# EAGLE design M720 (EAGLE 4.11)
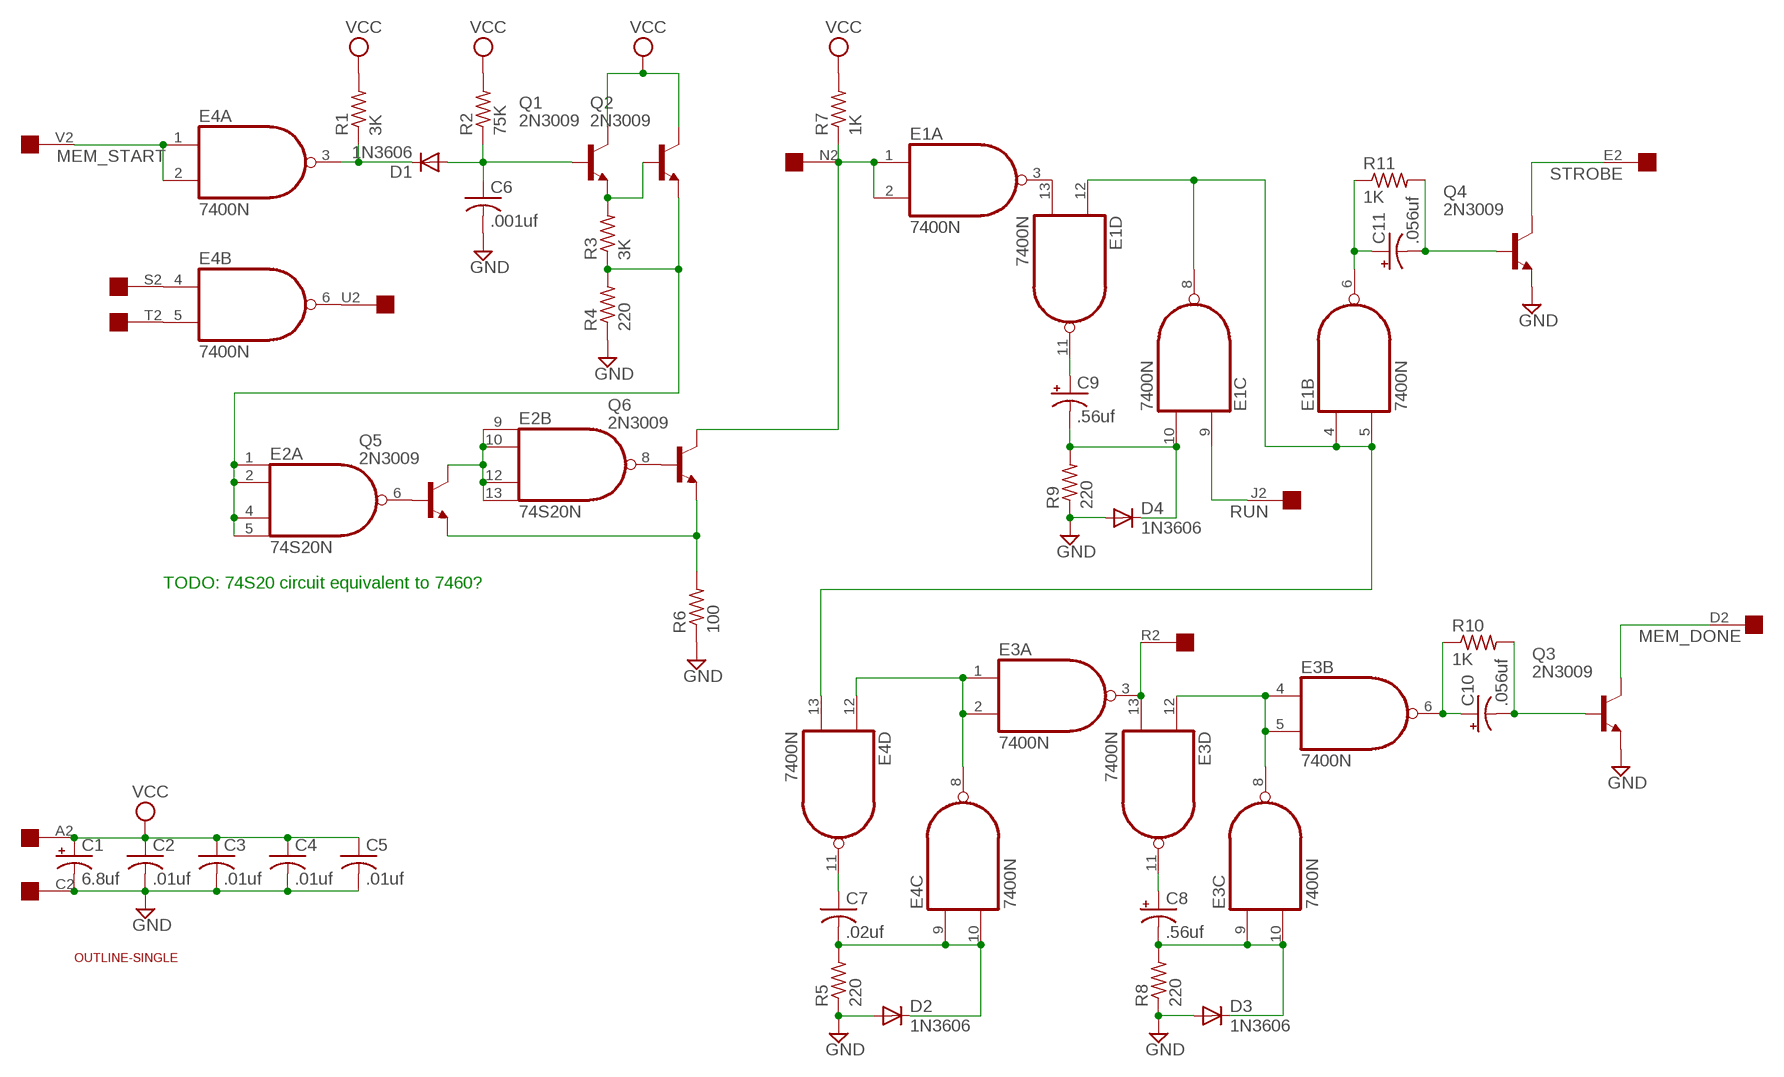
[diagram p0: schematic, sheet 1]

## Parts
C1  6.8uf  CPOL-USE15-5AXIAL  [E15-5]
C2  .01uf  C-US050-025X075  [C050-025X075]
C3  .01uf  C-US050-025X075  [C050-025X075]
C4  .01uf  C-US050-025X075  [C050-025X075]
C5  .01uf  C-US050-025X075  [C050-025X075]
C6  .001uf  C-US050-025X075  [C050-025X075]
C7  .02uf  C-US050-025X075  [C050-025X075]
C8  .56uf  CPOL-USB45181C  [B45181C]
C9  .56uf  CPOL-USB45181C  [B45181C]
C10  .056uf  CPOL-USB45181C  [B45181C]
C11  .056uf  CPOL-USB45181C  [B45181C]
D1  1N3606  1N4148  [DO35-10]
D2  1N3606  1N4148  [DO35-10]
D3  1N3606  1N4148  [DO35-10]
D4  1N3606  1N4148  [DO35-10]
E1  7400N  [DIL14]
E2  74S20N  [DIL14]
E3  7400N  [DIL14]
E4  7400N  [DIL14]
Q1  2N3009  2N2405  [TO5]
Q2  2N3009  2N2405  [TO5]
Q3  2N3009  2N2405  [TO5]
Q4  2N3009  2N2405  [TO5]
Q5  2N3009  2N2405  [TO5]
Q6  2N3009  2N2405  [TO5]
R1  3K  R-US_0207/10  [0207/10]
R2  75K  R-US_0207/10  [0207/10]
R3  3K  R-US_0207/10  [0207/10]
R4  220  R-US_0207/10  [0207/10]
R5  220  R-US_0207/10  [0207/10]
R6  100  R-US_0207/10  [0207/10]
R7  1K  R-US_0207/10  [0207/10]
R8  220  R-US_0207/10  [0207/10]
R9  220  R-US_0207/10  [0207/10]
R10  1K  R-US_0207/10  [0207/10]
R11  1K  R-US_0207/10  [0207/10]
U$1  OUTLINE-SINGLE  [SINGLE]
U$3  EDGE-1  [EDGE-CON1]

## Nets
GND [supply]: C1.- C2.2 C3.2 C4.2 C5.2 C6.2 D2.A D3.A D4.A Q3.1(E) Q4.1(E) R4.1 R5.1 R6.1 R8.1 R9.1 U$3.C2
MEM_DONE: Q3.3(C) U$3.D2
MEM_START: E4.1(A:I0) E4.2(A:I1) U$3.V2
N$1: E2.1(A:I0) E2.2(A:I1) E2.4(A:I2) E2.5(A:I3) Q2.1(E) R3.1 R4.2
N$2: D1.C E4.3(A:O) R1.1
N$3: C6.1 D1.A Q1.2(B) R2.1
N$4: Q1.1(E) Q2.2(B) R3.2
N$5: E4.4(B:I0) U$3.S2
N$6: E4.5(B:I1) U$3.T2
N$7: E4.6(B:O) U$3.U2
N$8: E1.1(A:I0) E1.2(A:I1) Q6.3(C) R7.1 U$3.N2
N$9: E1.3(A:O) E1.13(D:I1)
N$10: E1.4(B:I0) E1.5(B:I1) E1.8(C:O) E1.12(D:I0) E4.13(D:I1)
N$11: C7.2 D2.C E4.9(C:I0) E4.10(C:I1) R5.2
N$12: C9.+ E1.11(D:O)
N$13: C9.- D4.C E1.10(C:I1) R9.2
N$14: C11.+ E1.6(B:O) R11.1
N$15: C11.- Q4.2(B) R11.2
N$16: E3.1(A:I0) E3.2(A:I1) E4.8(C:O) E4.12(D:I0)
N$17: C7.1 E4.11(D:O)
N$18: E3.3(A:O) E3.13(D:I1) U$3.R2
N$19: E3.4(B:I0) E3.5(B:I1) E3.8(C:O) E3.12(D:I0)
N$20: E2.8(B:O) Q6.2(B)
N$21: C8.- D3.C E3.9(C:I0) E3.10(C:I1) R8.2
N$22: C8.+ E3.11(D:O)
N$23: C10.+ E3.6(B:O) R10.1
N$24: C10.- Q3.2(B) R10.2
N$25: E2.6(A:O) Q5.2(B)
N$26: E2.9(B:I0) E2.10(B:I1) E2.12(B:I2) E2.13(B:I3) Q5.3(C)
N$28: Q5.1(E) Q6.1(E) R6.2
RUN: E1.9(C:I0) U$3.J2
STROBE: Q4.3(C) U$3.E2
VCC [supply]: C1.+ C2.1 C3.1 C4.1 C5.1 Q1.3(C) Q2.3(C) R1.2 R2.2 R7.2 U$3.A2
Unconnected: U$3.B2 U$3.F2 U$3.H2 U$3.K2 U$3.L2 U$3.M2 U$3.P2

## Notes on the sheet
- TODO: 74S20 circuit equivalent to 7460?

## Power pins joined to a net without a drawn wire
GND: E1.7(P:GND) E2.7(P:GND) E3.7(P:GND) E4.7(P:GND)
VCC: E1.14(P:VCC) E2.14(P:VCC) E3.14(P:VCC) E4.14(P:VCC)

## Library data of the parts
C1 C8-C11 = rcl:CPOL-US: POLARIZED CAPACITOR, American symbol
C2-C7 = rcl:C-US: CAPACITOR, American symbol
D1-D4 = diode:1N4148: DIODE
E1 E3 E4 = 74xx-us:74*00: Quad 2-input NAND gate
E2 = 74xx-us:74*20: Dual 4-input NAND gate
Q1-Q6 = transistor:2N2405: NPN TRANSISTOR
R1-R11 = rcl:R-US_: RESISTOR, American symbol
U$1 = dec-con:OUTLINE-*: Board outlines for DEC boards.
U$3 = dec-con:EDGE-1: Single-Sided DEC Edge Connector -- (side 2)

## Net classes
1 supply: width 0.762 mm, drill 0.508 mm

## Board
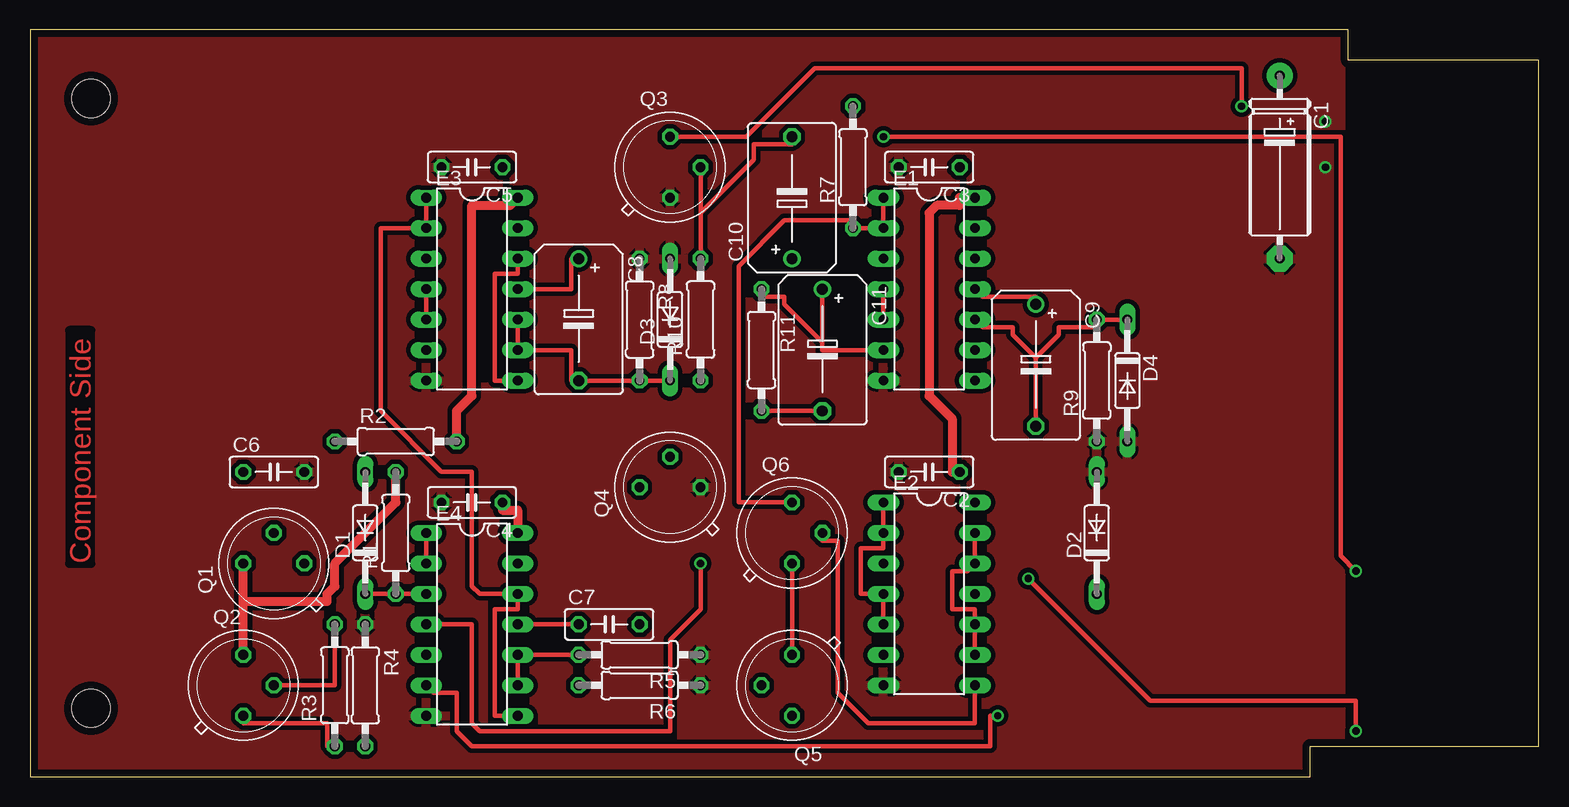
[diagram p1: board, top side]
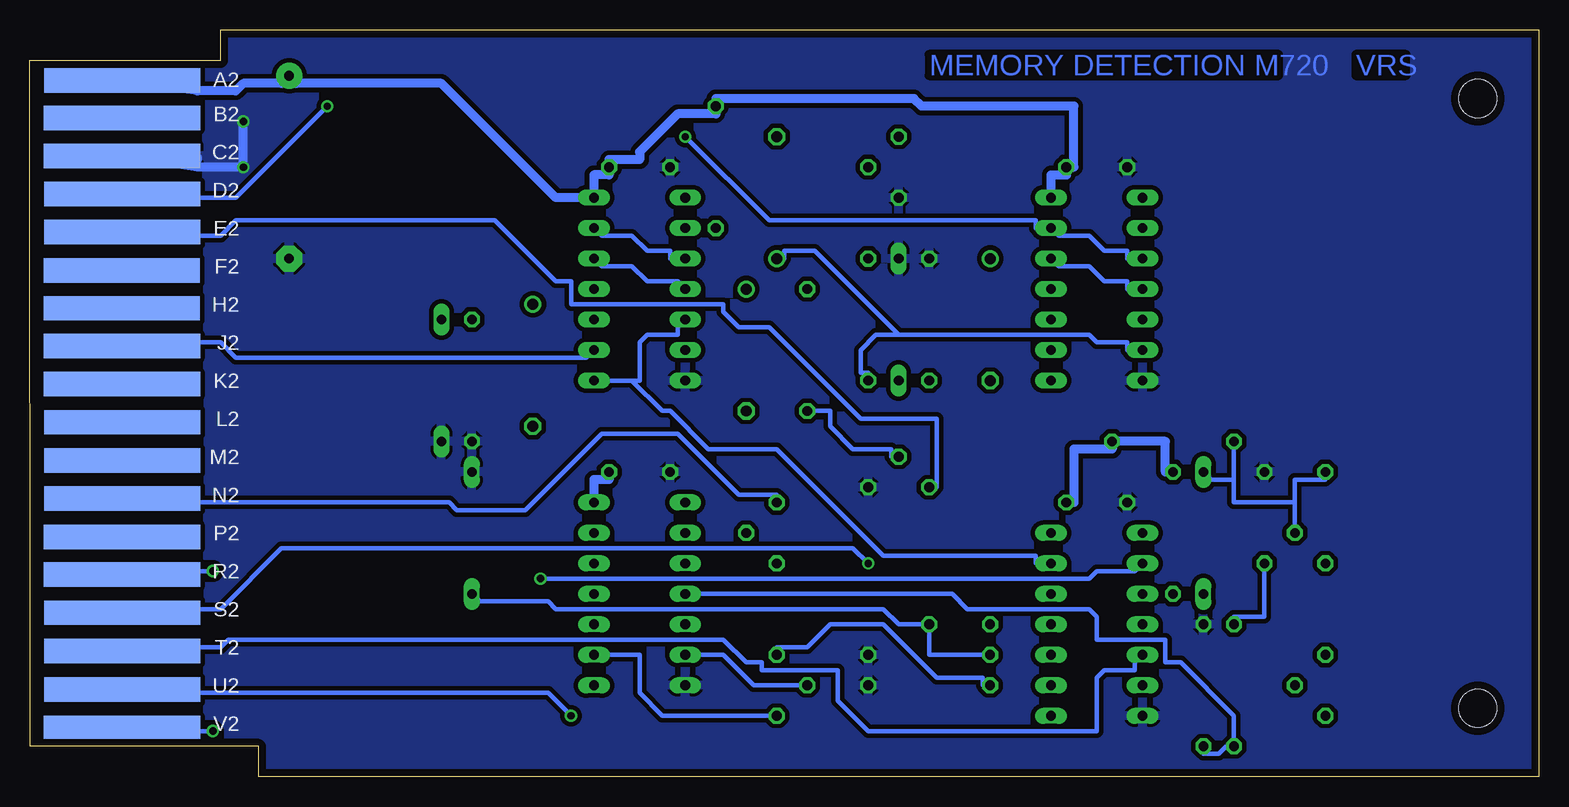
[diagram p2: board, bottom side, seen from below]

Size 125.73 x 62.23 mm. Coordinates in mm from the lower left corner, seen from the top.
Copper layers (1*16): Top 0.035mm / dielectric 1.5mm / Bottom 0.035mm
Design rules "15mils": minimum track width 15mil, minimum drill 24mil, track to track 15mil, track to pad 10mil, pad to pad 10mil, via to via 10mil, smd to smd 10mil, copper to edge 25mil, drill to drill 10mil, minimum pad ring 10mil, minimum via ring 8mil, stop-mask expansion 0mil, vias tented up to drill 0mil, thermal gap 10mil

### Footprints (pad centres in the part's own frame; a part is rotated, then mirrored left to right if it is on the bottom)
E15-5 = drill 0.813 pad 2.159 round: + -7.62,0 | drill 0.813 pad 2.159 octagon: - 7.62,0
C050-025X075 = drill 0.813 octagon: 1 -2.54,0; 2 2.54,0
B45181C = drill 0.914 round: + -5.08,0 | drill 0.914 octagon: - 5.08,0
DO35-10 = drill 0.813 long: A 5.08,0; C -5.08,0
DIL14 = drill 0.813 long: 1 -7.62,-3.81; 2 -5.08,-3.81; 3 -2.54,-3.81; 4 0,-3.81; 5 2.54,-3.81; 6 5.08,-3.81; 7 7.62,-3.81; 8 7.62,3.81; 9 5.08,3.81; 10 2.54,3.81; 11 0,3.81; 12 -2.54,3.81; 13 -5.08,3.81; 14 -7.62,3.81
TO5 = drill 0.813 octagon: 1 0,-2.54; 2 2.54,0; 3 0,2.54
0207/10 = drill 0.813 octagon: 1 -5.08,0; 2 5.08,0
SINGLE = hole 3.175: 120.65,56.515; 120.65,5.715
EDGE-CON1 = smd 13.017 x 2.032 bottom: A2 7.69,4.194; B2 7.668,7.328; C2 7.668,10.49; D2 7.693,13.665; E2 7.693,16.84; F2 7.642,20.041; H2 7.642,23.19; J2 7.668,26.34; K2 7.668,29.515; L2 7.693,32.69; M2 7.693,35.89; N2 7.693,39.04; P2 7.668,42.24; R2 7.668,45.39; S2 7.693,48.565; T2 7.693,51.74; U2 7.693,54.966 | smd 13.017 x 1.905 bottom: V2 7.668,58.102

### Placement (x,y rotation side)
C1  104.14,50.8 270 top
C2  74.93,25.4 180 top
C3  74.93,50.8 180 top
C4  36.83,22.86 180 top
C5  36.83,50.8 180 top
C6  20.32,25.4 0 top
C7  48.26,12.7 0 top
C8  45.72,38.1 270 top
C9  83.82,34.29 270 top
C10  63.5,48.26 90 top
C11  66.04,35.56 270 top
D1  27.94,20.32 90 top
D2  88.9,20.32 90 top
D3  53.34,38.1 90 top
D4  91.44,33.02 270 top
E1  74.93,40.64 270 top
E2  74.93,15.24 270 top
E3  36.83,40.64 270 top
E4  36.83,12.7 270 top
Q1  20.32,17.78 90 top
Q2  17.78,7.62 0 top
Q3  53.34,50.8 0 top
Q4  53.34,24.13 90 top
Q5  63.5,7.62 180 top
Q6  63.5,20.32 0 top
R1  30.48,20.32 90 top
R2  30.48,27.94 0 top
R3  25.4,7.62 90 top
R4  27.94,7.62 270 top
R5  50.8,10.16 180 top
R6  50.8,7.62 180 top
R7  68.58,50.8 90 top
R8  50.8,38.1 270 top
R9  88.9,33.02 90 top
R10  55.88,38.1 90 top
R11  60.96,35.56 270 top
U$1  125.73,62.23 180 top
U$3  125.73,62.23 180 top

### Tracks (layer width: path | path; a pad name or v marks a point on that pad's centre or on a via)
GND  (via drill 0.61)
  Bottom 0.762: 111.76,51.61 111.76,51.44 U$3.C2 111.76,50.8 v107.95,50.8 v107.95,54.61
  pour Bottom: 0,62.23 111.76,62.23 111.76,0 0,0
  pour Top: 0,62.23 109.22,62.23 109.22,0 0,0
MEM_DONE  (via drill 0.61)
  Top 0.381: v100.97,55.88 100.97,59.05 65.41,59.05 59.69,53.34 Q3.3
  Bottom 0.381: v100.97,55.88 108.58,48.26 111.76,48.26 U$3.D2
MEM_START  (via drill 0.61)
  Top 0.381: E4.2 E4.1 | v83.19,16.51 93.34,6.35 110.49,6.35 v110.49,3.81
  Bottom 0.381: v83.19,16.51 37.47,16.51 36.83,17.14 33.66,17.14 E4.2 | v110.49,3.81 111.76,3.81 U$3.V2
N$1
  Top 0.381: E2.5 E2.4 69.22,15.24 69.22,19.05 71.12,19.05 E2.2 E2.1 | Q2.1 17.78,4.45 24.77,4.45 24.77,2.54 R3.1
  Bottom 0.381: R4.2 27.94,1.91 26.67,1.91 26.04,2.54 R3.1 25.4,5.08 29.84,9.53 31.11,9.53 31.11,11.43 36.83,11.43 36.83,13.34 37.47,13.97 47.62,13.97 48.9,15.24 E2.4
N$2
  Top 0.381: D1.C R1.1 E4.3
N$3
  Bottom 0.381: 25.4,24.77 27.3,24.77 D1.A | 25.4,24.77 R2.1 | 20.32,22.86 20.32,24.77 17.78,24.77 C6.1 | Q1.2 20.32,22.86 | 25.4,24.77 25.4,22.86 20.32,22.86
N$4
  Top 0.381: Q2.2 25.4,7.62 R3.2
  Bottom 0.381: Q1.1 22.86,13.34 25.4,13.34 R3.2
N$5  (via drill 0.61)
  Top 0.381: v55.88,17.78 55.88,13.97 53.34,11.43 53.34,3.81 37.47,3.81 36.83,4.45 36.83,12.7 E4.4
  Bottom 0.381: v55.88,17.78 57.15,19.05 104.78,19.05 109.86,13.97 111.76,13.97 U$3.S2
N$6
  Bottom 0.381: E4.5 33.66,9.53 33.66,8.89 36.2,8.89 36.83,8.26 36.83,3.81 55.88,3.81 58.42,6.35 58.42,8.89 64.77,8.89 64.77,9.53 66.04,9.53 67.94,11.43 109.22,11.43 109.86,10.79 111.76,10.79 U$3.T2
N$7  (via drill 0.61)
  Top 0.381: E4.6 33.66,6.99 35.56,6.99 35.56,3.81 36.83,2.54 80.01,2.54 80.01,5.08 v80.64,5.08
  Bottom 0.381: v80.64,5.08 82.55,6.99 111.76,6.99 U$3.U2
N$8
  Top 0.381: Q6.3 59.05,22.86 59.05,42.55 62.87,46.35 68.58,46.35 R7.1 E1.2 E1.1
  Bottom 0.381: U$3.N2 111.76,22.86 90.81,22.86 90.17,22.23 84.45,22.23 78.11,28.57 71.75,28.57 66.67,23.5 63.5,23.5 Q6.3
N$9
  Bottom 0.381: E1.3 72.39,43.18 72.39,43.81 74.3,43.81 75.56,45.09 78.11,45.09 E1.13
N$10
  Top 0.381: E1.5 E1.4
  Bottom 0.381: E1.12 78.11,42.55 75.56,42.55 74.3,41.27 71.75,41.27 E1.4 | 75.56,33.02 73.03,30.48 72.39,30.48 69.22,27.3 63.5,27.3 54.61,18.41 41.91,18.41 41.91,17.78 E4.13 | 75.56,33.02 E1.8 | 75.56,33.02 74.93,33.02 74.93,36.2 74.3,36.83 71.75,36.83 71.75,37.47 E1.5
N$11
  Top 0.381: E4.9 E4.10 R5.2
  Bottom 0.381: R5.2 50.8,10.16 C7.2 53.34,12.7 54.61,13.97 81.92,13.97 82.55,14.61 88.27,14.61 D2.C
N$12
  Top 0.381: E1.11 79.38,40.01 83.82,40.01 C9.+
N$13
  Top 0.381: D4.C R9.2 88.9,37.47 85.72,37.47 85.72,36.83 83.82,34.92 | 83.82,34.92 81.92,36.83 81.92,37.47 79.38,37.47 E1.10 | C9.- 83.82,34.92
N$14
  Top 0.381: 66.04,36.2 66.04,35.56 E1.6 | 66.04,36.2 C11.+ | 66.04,36.2 62.87,39.37 62.87,40.01 60.96,40.01 R11.1
N$15
  Top 0.381: R11.2 C11.-
  Bottom 0.381: Q4.2 53.98,26.67 53.98,27.3 57.15,27.3 59.05,29.21 59.05,30.48 R11.2
N$16
  Top 0.381: E3.1 E3.2 29.21,45.72 29.21,30.48 34.29,25.4 36.83,25.4 36.83,15.88 37.47,15.24 E4.12 40.64,13.97 38.73,13.97 38.73,5.08 E4.8
N$17
  Top 0.381: E4.11 C7.1
N$18  (via drill 0.61)
  Top 0.381: v71.12,53.34 109.22,53.34 109.22,18.41 v110.49,17.14
  Bottom 0.381: E3.3 34.29,43.18 34.29,43.81 36.2,43.81 37.47,45.09 40.01,45.09 E3.13 41.91,45.72 41.91,46.35 64.14,46.35 v71.12,53.34 | v110.49,17.14 111.76,17.14 U$3.R2
N$19
  Top 0.381: E3.5 E3.4 | E3.8 38.73,33.02 38.73,41.91 40.64,41.91 E3.12
  Bottom 0.381: E3.4 34.29,40.64 34.29,41.27 36.2,41.27 37.47,42.55 40.01,42.55 E3.12
N$20
  Top 0.381: Q6.2 66.04,19.68 67.31,19.68 67.31,6.99 69.85,4.45 78.74,4.45 E2.8
N$21
  Top 0.381: E3.10 E3.9 45.09,35.56 45.09,33.02 C8.- R8.2 D3.C
N$22
  Top 0.381: E3.11 45.09,40.64 45.09,43.18 C8.+
N$23
  Bottom 0.381: 53.34,36.83 55.24,36.83 56.52,35.56 56.52,33.66 55.88,33.66 R10.1 | 53.34,36.83 37.47,36.83 36.83,36.2 34.29,36.2 34.29,35.56 E3.6 | 53.34,36.83 60.33,43.81 62.87,43.81 62.87,43.18 C10.+
N$24
  Top 0.381: R10.2 55.88,46.99 | 55.88,46.99 Q3.2 | 55.88,46.99 60.33,51.44 60.33,52.7 63.5,52.7 C10.-
N$25
  Bottom 0.381: Q5.2 65.41,7.62 67.94,10.16 E2.6
N$26
  Top 0.381: E2.13 E2.12 78.11,17.14 76.83,17.14 76.83,13.97 78.74,13.97 E2.10 E2.9
  Bottom 0.381: Q5.3 73.03,5.08 74.93,6.99 74.93,10.16 E2.9
N$28
  Top 0.381: Q5.1 Q6.1
  Bottom 0.381: R6.2 46.35,7.62 46.35,8.26 50.16,8.26 54.61,12.7 59.05,12.7 60.96,10.79 63.5,10.79 Q5.1
RUN
  Bottom 0.381: E1.9 79.38,34.92 108.58,34.92 109.86,36.2 111.76,36.2 U$3.J2
STROBE
  Bottom 0.381: Q4.3 50.16,24.13 50.16,29.84 56.52,29.84 64.14,37.47 66.67,37.47 67.94,38.73 67.94,39.37 80.64,39.37 80.64,41.27 81.92,41.27 87,46.35 108.58,46.35 109.86,45.09 111.76,45.09 U$3.E2
VCC
  Top 0.762: C4.1 39.37,22.23 40.64,22.23 E4.14 | E3.14 40.01,47.62 36.83,47.62 36.83,31.75 35.56,30.48 R2.2 | C2.1 76.83,25.4 76.83,29.84 74.93,31.75 74.93,46.99 75.56,47.62 77.47,47.62 77.47,48.26 E1.14 | Q2.3 17.78,14.61 | 17.78,14.61 Q1.3 | 17.78,14.61 24.77,14.61 24.77,15.24 25.4,15.88 25.4,17.78 30.48,22.86 R1.2
  Bottom 0.762: E3.14 40.64,50.16 39.37,50.16 C5.1 38.73,50.8 38.73,55.88 51.44,55.88 52.07,56.52 68.58,56.52 R7.2 68.58,55.24 71.75,55.24 74.93,52.07 74.93,51.44 77.47,51.44 C3.1 77.47,50.16 78.74,50.16 E1.14 81.92,48.26 91.44,57.78 103.5,57.78 C1.+ 104.78,57.78 107.95,57.78 108.58,57.15 111.76,57.15 U$3.A2 | R1.2 31.11,25.4 31.11,27.94 R2.2 35.56,27.3 38.73,27.3 38.73,22.86 C4.1 | E2.14 78.74,24.77 77.47,24.77 C2.1

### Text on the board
Top: Component Side
Bottom: VRS | MEMORY DETECTION M720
